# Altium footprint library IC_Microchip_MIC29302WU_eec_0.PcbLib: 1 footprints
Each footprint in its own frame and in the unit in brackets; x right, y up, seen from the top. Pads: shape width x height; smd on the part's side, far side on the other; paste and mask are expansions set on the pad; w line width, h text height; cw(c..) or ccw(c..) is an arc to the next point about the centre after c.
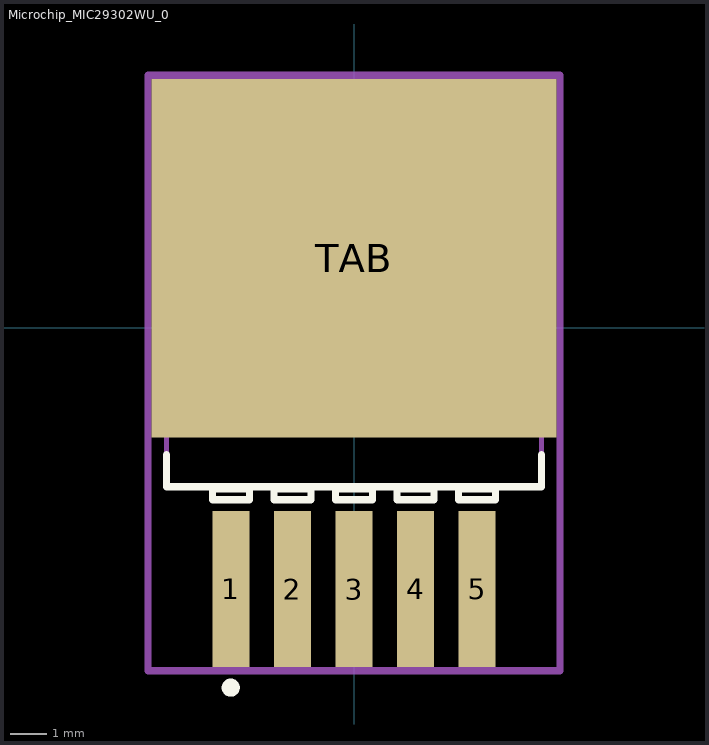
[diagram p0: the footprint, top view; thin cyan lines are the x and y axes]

## Microchip_MIC29302WU_0 [mm]
pads (6):
  rect 1.02x4.32 smd paste+0 mask+0: 1(-3.4,-7.219) 2(-1.7,-7.219) 3(0,-7.219) 4(1.7,-7.219) 5(3.4,-7.219)
  rect 11.18x9.91 smd paste+0 mask+0: TAB(0,1.926)
Top Overlay:
  circle w0.25: c-3.407,-9.944 r0.125
  lines w0.2: -5.182,-4.39 5.182,-4.39 ; -5.18,-4.39 -5.18,-3.5 ; 5.182,-4.39 5.182,-3.5 ; -3.91,-4.75 -2.89,-4.75 -2.89,-4.45 -3.91,-4.45 -3.91,-4.75 ; -2.21,-4.75 -1.19,-4.75 -1.19,-4.45 -2.21,-4.45 -2.21,-4.75 ; -0.51,-4.75 0.51,-4.75 0.51,-4.45 -0.51,-4.45 -0.51,-4.75 ; 1.19,-4.75 2.21,-4.75 2.21,-4.45 1.19,-4.45 1.19,-4.75 ; 2.89,-4.75 3.91,-4.75 3.91,-4.45 2.89,-4.45 2.89,-4.75
Mechanical 10:
  lines w0.2: -5.69,-9.479 5.69,-9.479 5.69,6.981 -5.69,6.981 -5.69,-9.479
  text ".Designator" at 0,-1.249 h1
Mechanical 12:
  lines w0.15: -5.182,-4.39 5.182,-4.39 5.182,4.39 -5.182,4.39 -5.182,-4.39
Mechanical 15:
  lines w0.1: -1.707,0 1.707,0 ; 0,-1.707 0,1.707
  lines w0.2: -5.69,-9.479 5.69,-9.479 5.69,6.981 -5.69,6.981 -5.69,-9.479
3D body "3dmodel.step": height 0.25, standoff 0, extent -5.69,-9.479 5.69,6.981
